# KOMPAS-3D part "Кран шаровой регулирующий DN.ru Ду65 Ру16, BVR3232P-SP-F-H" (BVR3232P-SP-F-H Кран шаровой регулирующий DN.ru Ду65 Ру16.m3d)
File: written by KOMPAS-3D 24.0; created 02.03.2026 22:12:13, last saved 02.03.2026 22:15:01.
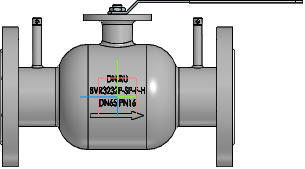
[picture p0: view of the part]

Document properties: Автор: Максим; Полное имя файла: BVR3232P-SP-F-H - Кран шаровой регулирующий DN.ru  Ду65 Ру16.cdw

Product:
- Body: Тело 1  | qty 1
    Масса: 22.220437
- Part/product: Кран шаровой регулирующий DN.ru Ду65 Ру16  | designation BVR3232P-SP-F-H
    Масса: 12.5
    Раздел спецификации: Прочие изделия
    Форматы листов документа: A3
    Примечание: D160-69423

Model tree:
1. Операция без истории:1

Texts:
  BVR3232P-SP-F-H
